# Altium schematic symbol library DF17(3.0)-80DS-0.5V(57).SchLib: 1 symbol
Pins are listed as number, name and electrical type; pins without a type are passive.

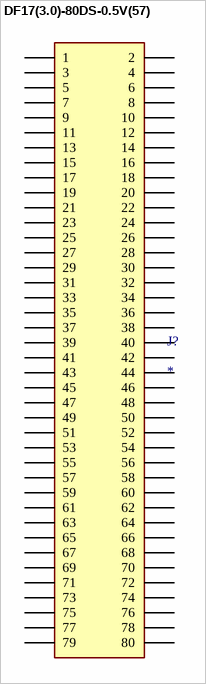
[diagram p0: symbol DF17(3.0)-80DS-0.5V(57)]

## DF17(3.0)-80DS-0.5V(57)
designator J?
Äáº§u ná»‘i 80 chÃ¢n, tiáº¿p Ä‘iá»ƒm dáº£i trung tÃ¢m, máº¡ vÃ ng, gáº¯n ná»•i.; MF: Hirose; MP: DF17(3.0)-80DS-0.5V(57)
footprint HRS_DF17(3.0)-80DS-0.5V(57)
pins: 1, 2, 3, 4, 5, 6, 7, 8, 9, 10, 11, 12, 13, 14, 15, 16, 17, 18, 19, 20, 21, 22, 23, 24, 25, 26, 27, 28, 29, 30, 31, 32, 33, 34, 35, 36, 37, 38, 39, 40, 41, 42, 43, 44, 45, 46, 47, 48, 49, 50, 51, 52, 53, 54, 55, 56, 57, 58, 59, 60, 61, 62, 63, 64, 65, 66, 67, 68, 69, 70, 71, 72, 73, 74, 75, 76, 77, 78, 79, 80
